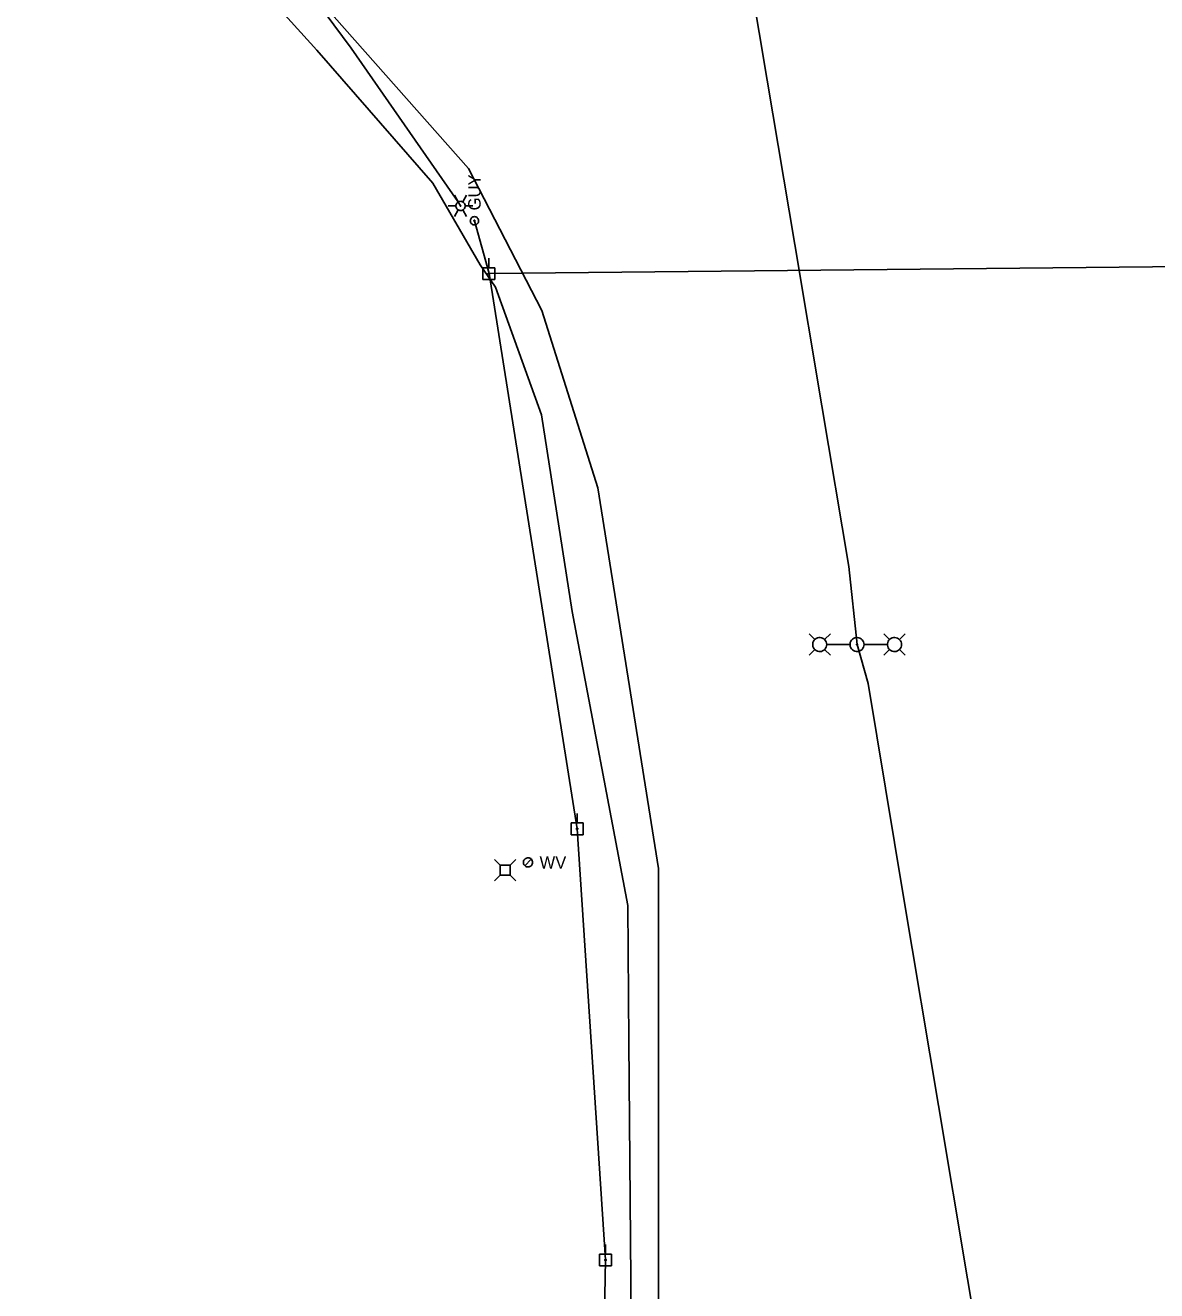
# Model space of a CAD drawing. Extents: x 596028 to 606371, y 330010 to 403088.
# Drawn here: x 604096 to 604446.4, y 338470.7 to 338862.5 of the extents above; entities that cross this region are included whole.
import ezdxf

# ---------------------------------------------------------------- set-up
doc = ezdxf.new("R2010")
doc.units = 0
for name, color, linetype in [('E_FTMS_Conduit', 7, 'Continuous'), ('E_LTG', 7, 'Continuous'), ('E_LTG_CID', 7, 'Continuous'), ('E_UTL_AG_Bold', 7, 'Continuous'), ('E_UTL_E', 7, 'Continuous'), ('E_UTL_EGuyWire', 7, 'Continuous'), ('E_UTL_EPowerPole', 7, 'Continuous'), ('E_UTL_FO_UG_QWEST', 7, 'Continuous'), ('E_UTL_Overhead', 7, 'Continuous'), ('E_UTL_W', 7, 'Continuous')]:
    doc.layers.add(name, color=color, linetype=linetype)

# ---------------------------------------------------------------- blocks, each defined once
blk = doc.blocks.new('ACAD_PROXY_ENTITY_17')
at = {"layer": 'E_UTL_AG_Bold'}
for points in [[(1842923.4, 1030440.8), (1842918.1, 1030446.1)], [(1842932.9, 1030440.8), (1842923.4, 1030440.8)], [(1842923.4, 1030440.8), (1842923.4, 1030431.4)], [(1842932.9, 1030440.8), (1842938.2, 1030446.1)], [(1842932.9, 1030431.4), (1842932.9, 1030440.8)], [(1842923.4, 1030431.4), (1842918.1, 1030426)], [(1842923.4, 1030431.4), (1842932.9, 1030431.4)], [(1842932.9, 1030431.4), (1842938.2, 1030426)]]:
    blk.add_lwpolyline(points, dxfattribs=at)

msp = doc.modelspace()

# ---------------------------------------------------------------- linework, layer by layer
at = {"layer": 'E_FTMS_Conduit'}
for points in [[(604292.05, 338601.41), (604273.29, 338719.32), (604255.92, 338774.24), (604233.24, 338818.17), (604114.89, 338951.98)], [(604292.05, 338112.99), (604292.05, 338601.41)]]:
    msp.add_lwpolyline(points, dxfattribs=at)
at = {"layer": 'E_LTG'}
for points in [[(604226.96, 338806.58), (604229.35, 338806.58)], [(604230.06, 338807.82), (604228.87, 338809.88)], [(604232.2, 338806.58), (604232.18, 338806.85), (604232.1, 338807.12), (604231.98, 338807.36), (604231.81, 338807.57), (604231.6, 338807.75), (604231.37, 338807.88), (604231.11, 338807.97), (604230.84, 338808.01), (604230.57, 338808), (604230.31, 338807.93), (604230.06, 338807.82), (604229.84, 338807.66), (604229.65, 338807.47), (604229.51, 338807.24), (604229.4, 338806.99), (604229.35, 338806.72), (604229.35, 338806.45), (604229.4, 338806.18), (604229.51, 338805.93), (604229.65, 338805.7), (604229.84, 338805.5), (604230.06, 338805.35), (604230.31, 338805.23), (604230.57, 338805.17), (604230.84, 338805.16), (604231.11, 338805.2), (604231.37, 338805.28), (604231.6, 338805.42), (604231.81, 338805.6), (604231.98, 338805.81), (604232.1, 338806.05), (604232.18, 338806.31), (604232.2, 338806.58)], [(604232.2, 338806.58), (604232.18, 338806.85), (604232.1, 338807.12), (604231.98, 338807.36), (604231.81, 338807.57), (604231.6, 338807.75), (604231.37, 338807.88), (604231.11, 338807.97), (604230.84, 338808.01), (604230.57, 338808), (604230.31, 338807.93), (604230.06, 338807.82), (604229.84, 338807.66), (604229.65, 338807.47), (604229.51, 338807.24), (604229.4, 338806.99), (604229.35, 338806.72), (604229.35, 338806.45), (604229.4, 338806.18), (604229.51, 338805.93), (604229.65, 338805.7), (604229.84, 338805.5), (604230.06, 338805.35), (604230.31, 338805.23), (604230.57, 338805.17), (604230.84, 338805.16), (604231.11, 338805.2), (604231.37, 338805.28), (604231.6, 338805.42), (604231.81, 338805.6), (604231.98, 338805.81), (604232.1, 338806.05), (604232.18, 338806.31), (604232.2, 338806.58)], [(604232.2, 338806.58), (604232.18, 338806.85), (604232.1, 338807.12), (604231.98, 338807.36), (604231.81, 338807.57), (604231.6, 338807.75), (604231.37, 338807.88), (604231.11, 338807.97), (604230.84, 338808.01), (604230.57, 338808), (604230.31, 338807.93), (604230.06, 338807.82), (604229.84, 338807.66), (604229.65, 338807.47), (604229.51, 338807.24), (604229.4, 338806.99), (604229.35, 338806.72), (604229.35, 338806.45), (604229.4, 338806.18), (604229.51, 338805.93), (604229.65, 338805.7), (604229.84, 338805.5), (604230.06, 338805.35), (604230.31, 338805.23), (604230.57, 338805.17), (604230.84, 338805.16), (604231.11, 338805.2), (604231.37, 338805.28), (604231.6, 338805.42), (604231.81, 338805.6), (604231.98, 338805.81), (604232.1, 338806.05), (604232.18, 338806.31), (604232.2, 338806.58)], [(604230.89, 338806.58), (604230.89, 338806.61), (604230.89, 338806.63), (604230.88, 338806.65), (604230.86, 338806.67), (604230.84, 338806.68), (604230.83, 338806.69), (604230.8, 338806.7), (604230.78, 338806.7), (604230.76, 338806.7), (604230.74, 338806.7), (604230.72, 338806.69), (604230.7, 338806.67), (604230.68, 338806.66), (604230.67, 338806.64), (604230.66, 338806.62), (604230.66, 338806.6), (604230.66, 338806.57), (604230.66, 338806.55), (604230.67, 338806.53), (604230.68, 338806.51), (604230.7, 338806.49), (604230.72, 338806.48), (604230.74, 338806.47), (604230.76, 338806.47), (604230.78, 338806.47), (604230.8, 338806.47), (604230.83, 338806.48), (604230.84, 338806.49), (604230.86, 338806.5), (604230.88, 338806.52), (604230.89, 338806.54), (604230.89, 338806.56), (604230.89, 338806.58)], [(604231.49, 338807.82), (604232.68, 338809.88)], [(604232.2, 338806.58), (604234.59, 338806.58)], [(604228.87, 338803.28), (604230.06, 338805.35)], [(604232.68, 338803.28), (604231.49, 338805.35)], [(604340.47, 338672.3), (604338.69, 338674.08)], [(604344.17, 338670.78), (604344.13, 338671.19), (604344.02, 338671.59), (604343.83, 338671.96), (604343.57, 338672.28), (604343.26, 338672.56), (604342.9, 338672.76), (604342.51, 338672.9), (604342.1, 338672.96), (604341.69, 338672.94), (604341.28, 338672.84), (604340.91, 338672.67), (604340.57, 338672.43), (604340.29, 338672.13), (604340.06, 338671.78), (604339.91, 338671.4), (604339.83, 338670.99), (604339.83, 338670.58), (604339.91, 338670.17), (604340.06, 338669.79), (604340.29, 338669.44), (604340.57, 338669.14), (604340.91, 338668.9), (604341.28, 338668.73), (604341.69, 338668.63), (604342.1, 338668.61), (604342.51, 338668.67), (604342.9, 338668.8), (604343.26, 338669.01), (604343.57, 338669.28), (604343.83, 338669.61), (604344.02, 338669.97), (604344.13, 338670.37), (604344.17, 338670.78)], [(604343.52, 338672.3), (604345.3, 338674.08)], [(604355.74, 338670.78), (604355.7, 338671.19), (604355.58, 338671.59), (604355.39, 338671.96), (604355.14, 338672.28), (604354.82, 338672.55), (604354.47, 338672.76), (604354.07, 338672.9), (604353.66, 338672.96), (604353.25, 338672.94), (604352.85, 338672.84), (604352.47, 338672.67), (604352.14, 338672.43), (604351.85, 338672.13), (604351.63, 338671.78), (604351.47, 338671.4), (604351.4, 338670.99), (604351.4, 338670.58), (604351.47, 338670.17), (604351.63, 338669.79), (604351.85, 338669.44), (604352.14, 338669.14), (604352.47, 338668.9), (604352.85, 338668.73), (604353.25, 338668.63), (604353.66, 338668.61), (604354.07, 338668.67), (604354.47, 338668.8), (604354.82, 338669.01), (604355.14, 338669.28), (604355.39, 338669.61), (604355.58, 338669.97), (604355.7, 338670.37), (604355.74, 338670.78)], [(604363.64, 338672.31), (604361.86, 338674.08)], [(604367.34, 338670.78), (604367.3, 338671.19), (604367.18, 338671.59), (604366.99, 338671.96), (604366.74, 338672.28), (604366.43, 338672.55), (604366.07, 338672.76), (604365.68, 338672.9), (604365.27, 338672.96), (604364.85, 338672.94), (604364.45, 338672.84), (604364.08, 338672.67), (604363.74, 338672.43), (604363.45, 338672.13), (604363.23, 338671.78), (604363.08, 338671.4), (604363, 338670.99), (604363, 338670.58), (604363.08, 338670.17), (604363.23, 338669.79), (604363.45, 338669.44), (604363.74, 338669.14), (604364.08, 338668.9), (604364.45, 338668.73), (604364.85, 338668.63), (604365.27, 338668.61), (604365.68, 338668.67), (604366.07, 338668.8), (604366.43, 338669.01), (604366.74, 338669.28), (604366.99, 338669.61), (604367.18, 338669.97), (604367.3, 338670.37), (604367.34, 338670.78)], [(604366.69, 338672.31), (604368.47, 338674.08)], [(604340.47, 338669.26), (604338.69, 338667.48)], [(604343.52, 338669.26), (604345.3, 338667.48)], [(604344.21, 338670.78), (604351.39, 338670.78)], [(604353.73, 338670.78), (604353.72, 338670.81), (604353.72, 338670.84), (604353.7, 338670.87), (604353.68, 338670.9), (604353.66, 338670.92), (604353.63, 338670.93), (604353.6, 338670.94), (604353.57, 338670.95), (604353.54, 338670.95), (604353.51, 338670.94), (604353.48, 338670.93), (604353.45, 338670.91), (604353.43, 338670.89), (604353.41, 338670.86), (604353.4, 338670.83), (604353.4, 338670.8), (604353.4, 338670.77), (604353.4, 338670.74), (604353.41, 338670.71), (604353.43, 338670.68), (604353.45, 338670.66), (604353.48, 338670.64), (604353.51, 338670.63), (604353.54, 338670.62), (604353.57, 338670.62), (604353.6, 338670.62), (604353.63, 338670.63), (604353.66, 338670.65), (604353.68, 338670.67), (604353.7, 338670.69), (604353.72, 338670.72), (604353.72, 338670.75), (604353.73, 338670.78)], [(604362.95, 338670.78), (604355.77, 338670.78)], [(604363.64, 338669.26), (604361.86, 338667.48)], [(604366.69, 338669.26), (604368.47, 338667.48)]]:
    msp.add_lwpolyline(points, dxfattribs=at)
at = {"layer": 'E_LTG_CID'}
for points in [[(604230.78, 338806.58), (604229.94, 338807.94), (604196.91, 338855.38), (604162.36, 338902.09), (604137.73, 338945.81), (604096.01, 339002.71)], [(604353.57, 338670.76), (604353.57, 338670.76), (604350.99, 338694.94), (604342.69, 338744.69), (604334.31, 338794.61), (604325.73, 338845.48), (604318.29, 338889.92)], [(604448.04, 338113.09), (604444.75, 338124.83), (604443.41, 338133.07), (604442.71, 338144.36), (604440.69, 338156.93), (604434.52, 338195.65), (604426.45, 338242.49), (604418.51, 338290.37), (604411.48, 338331.4), (604406.05, 338365.11), (604400.32, 338390.47), (604399.21, 338398.84), (604398.47, 338411.01), (604387.76, 338474.36), (604378.81, 338528.04), (604367.93, 338592.68), (604362.35, 338626.27), (604357.03, 338658.73), (604353.57, 338670.76)]]:
    msp.add_lwpolyline(points, dxfattribs=at)
at = {"layer": 'E_UTL_EGuyWire'}
msp.add_line((604235.09, 338801.99), (604239.6, 338785.61), dxfattribs=at)
for points in [[(604235.09, 338803.28), (604234.85, 338803.25), (604234.62, 338803.19), (604234.4, 338803.07), (604234.21, 338802.92), (604234.05, 338802.74), (604233.93, 338802.53), (604233.85, 338802.3), (604233.81, 338802.06), (604233.82, 338801.81), (604233.88, 338801.57), (604233.98, 338801.35), (604234.12, 338801.15), (604234.3, 338800.99), (604234.5, 338800.85), (604234.73, 338800.76), (604234.97, 338800.72), (604235.21, 338800.72), (604235.45, 338800.76), (604235.68, 338800.85), (604235.89, 338800.99), (604236.06, 338801.15), (604236.2, 338801.35), (604236.31, 338801.57), (604236.36, 338801.81), (604236.37, 338802.06), (604236.34, 338802.3), (604236.26, 338802.53), (604236.14, 338802.74), (604235.98, 338802.92), (604235.79, 338803.07), (604235.57, 338803.19), (604235.34, 338803.25), (604235.09, 338803.28)], [(604235.09, 338802.15), (604235.06, 338802.15), (604235.03, 338802.14), (604235.01, 338802.13), (604234.98, 338802.11), (604234.96, 338802.09), (604234.95, 338802.06), (604234.94, 338802.03), (604234.93, 338802), (604234.93, 338801.97), (604234.94, 338801.94), (604234.95, 338801.91), (604234.97, 338801.89), (604234.99, 338801.87), (604235.02, 338801.85), (604235.05, 338801.84), (604235.08, 338801.83), (604235.11, 338801.83), (604235.14, 338801.84), (604235.17, 338801.85), (604235.19, 338801.87), (604235.21, 338801.89), (604235.23, 338801.91), (604235.24, 338801.94), (604235.25, 338801.97), (604235.25, 338802), (604235.25, 338802.03), (604235.24, 338802.06), (604235.22, 338802.09), (604235.2, 338802.11), (604235.18, 338802.13), (604235.15, 338802.14), (604235.12, 338802.15), (604235.09, 338802.15)]]:
    msp.add_lwpolyline(points, dxfattribs=at)
at = {"layer": 'E_UTL_EPowerPole'}
for points in [[(604241.41, 338787.46), (604237.72, 338787.46)], [(604237.72, 338787.46), (604237.72, 338783.77)], [(604239.57, 338787.46), (604239.57, 338790.37)], [(604241.41, 338783.77), (604241.41, 338787.46)], [(604237.72, 338783.77), (604241.41, 338783.77)], [(604239.84, 338785.61), (604239.83, 338785.66), (604239.82, 338785.7), (604239.8, 338785.74), (604239.77, 338785.78), (604239.74, 338785.81), (604239.7, 338785.83), (604239.66, 338785.85), (604239.61, 338785.85), (604239.57, 338785.85), (604239.52, 338785.84), (604239.48, 338785.82), (604239.44, 338785.8), (604239.41, 338785.76), (604239.39, 338785.72), (604239.37, 338785.68), (604239.36, 338785.64), (604239.36, 338785.59), (604239.37, 338785.55), (604239.39, 338785.51), (604239.41, 338785.47), (604239.44, 338785.43), (604239.48, 338785.41), (604239.52, 338785.39), (604239.57, 338785.38), (604239.61, 338785.38), (604239.66, 338785.38), (604239.7, 338785.4), (604239.74, 338785.42), (604239.77, 338785.45), (604239.8, 338785.49), (604239.82, 338785.53), (604239.83, 338785.57), (604239.84, 338785.61)], [(604266.87, 338615.58), (604266.87, 338618.49)], [(604268.71, 338615.58), (604265.02, 338615.58)], [(604265.02, 338615.58), (604265.02, 338611.89)], [(604268.71, 338611.89), (604268.71, 338615.58)], [(604265.02, 338611.89), (604268.71, 338611.89)], [(604267.14, 338613.74), (604267.13, 338613.79), (604267.12, 338613.83), (604267.1, 338613.87), (604267.07, 338613.9), (604267.04, 338613.93), (604267, 338613.96), (604266.96, 338613.97), (604266.91, 338613.98), (604266.87, 338613.98), (604266.82, 338613.97), (604266.78, 338613.95), (604266.74, 338613.92), (604266.71, 338613.89), (604266.69, 338613.85), (604266.67, 338613.81), (604266.66, 338613.76), (604266.66, 338613.72), (604266.67, 338613.67), (604266.69, 338613.63), (604266.71, 338613.59), (604266.74, 338613.56), (604266.78, 338613.53), (604266.82, 338613.51), (604266.87, 338613.5), (604266.91, 338613.5), (604266.96, 338613.51), (604267, 338613.52), (604267.04, 338613.55), (604267.07, 338613.58), (604267.1, 338613.61), (604267.12, 338613.65), (604267.13, 338613.69), (604267.14, 338613.74)], [(604275.67, 338482.07), (604275.67, 338484.98)], [(604277.51, 338482.07), (604273.82, 338482.07)], [(604273.82, 338482.07), (604273.82, 338478.38)], [(604277.51, 338478.38), (604277.51, 338482.07)], [(604273.82, 338478.38), (604277.51, 338478.38)], [(604275.94, 338480.23), (604275.93, 338480.27), (604275.92, 338480.31), (604275.9, 338480.35), (604275.87, 338480.39), (604275.84, 338480.42), (604275.8, 338480.44), (604275.76, 338480.46), (604275.71, 338480.46), (604275.67, 338480.46), (604275.62, 338480.45), (604275.58, 338480.43), (604275.54, 338480.41), (604275.51, 338480.37), (604275.49, 338480.33), (604275.47, 338480.29), (604275.46, 338480.25), (604275.46, 338480.2), (604275.47, 338480.16), (604275.49, 338480.12), (604275.51, 338480.08), (604275.54, 338480.05), (604275.58, 338480.02), (604275.62, 338480), (604275.67, 338479.99), (604275.71, 338479.99), (604275.76, 338479.99), (604275.8, 338480.01), (604275.84, 338480.03), (604275.87, 338480.06), (604275.9, 338480.1), (604275.92, 338480.14), (604275.93, 338480.18), (604275.94, 338480.23)]]:
    msp.add_lwpolyline(points, dxfattribs=at)
at = {"layer": 'E_UTL_FO_UG_QWEST'}
msp.add_lwpolyline([(604300.01, 338102.28), (604292.13, 338113.02), (604282.74, 338120.05), (604281.87, 338122.38), (604281.87, 338122.39), (604281.87, 338122.34), (604281.87, 338122.38), (604281.94, 338206.42), (604279.01, 338273.53), (604281.87, 338308.37), (604284.38, 338375.78), (604282.88, 338547.85), (604282.59, 338589.97), (604265.37, 338681.02), (604255.89, 338741.85), (604241.59, 338781.41), (604236.84, 338788.31), (604222.2, 338813.62), (604186.27, 338854.85), (604152.41, 338892.26)], dxfattribs=at)
at = {"layer": 'E_UTL_Overhead'}
msp.add_line((604239.6, 338785.61), (604484.36, 338788.16), dxfattribs=at)
msp.add_lwpolyline([(604269.62, 338062.62), (604269.81, 338193.31), (604272.87, 338331.43), (604275.7, 338480.23), (604266.9, 338613.74), (604239.6, 338785.61)], dxfattribs=at)
at = {"layer": 'E_UTL_W'}
for points in [[(604253.11, 338603.32), (604253.08, 338603.59), (604253.01, 338603.85), (604252.88, 338604.09), (604252.71, 338604.31), (604252.51, 338604.48), (604252.27, 338604.62), (604252.02, 338604.71), (604251.75, 338604.75), (604251.48, 338604.73), (604251.22, 338604.67), (604250.97, 338604.56), (604250.75, 338604.4), (604250.56, 338604.2), (604250.41, 338603.97), (604250.31, 338603.72), (604250.26, 338603.46), (604250.26, 338603.19), (604250.31, 338602.92), (604250.41, 338602.67), (604250.56, 338602.44), (604250.75, 338602.24), (604250.97, 338602.09), (604251.22, 338601.97), (604251.48, 338601.91), (604251.75, 338601.9), (604252.02, 338601.94), (604252.27, 338602.02), (604252.51, 338602.16), (604252.71, 338602.34), (604252.88, 338602.55), (604253.01, 338602.79), (604253.08, 338603.05), (604253.11, 338603.32)], [(604250.67, 338602.31), (604252.69, 338604.33)]]:
    msp.add_lwpolyline(points, dxfattribs=at)

# ---------------------------------------------------------------- block references
at = {"layer": 'E_UTL_E', "xscale": 0.32808333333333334, "yscale": 0.32808333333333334}
msp.add_blockref('ACAD_PROXY_ENTITY_17', (-389.39, 531.98), dxfattribs=at)

# ---------------------------------------------------------------- texts
at = {"layer": 'E_UTL_EGuyWire'}
msp.add_text('GUY', height=3.85, rotation=90, dxfattribs=at).set_placement((604237.02, 338805.2))
at = {"layer": 'E_UTL_W'}
msp.add_text('WV', height=3.85, dxfattribs=at).set_placement((604255.25, 338601.4))

doc.saveas('drawing.dxf')
